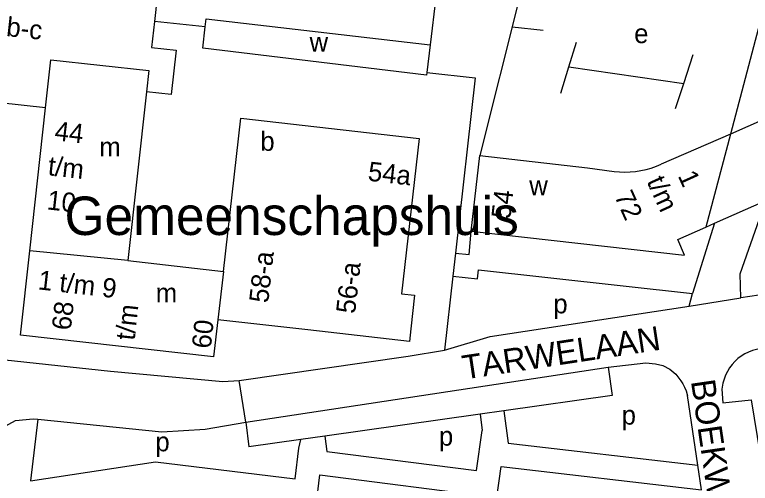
# Model space of a CAD drawing. Extents: x 161936 to 163647, y 386450 to 388633.
# Drawn here: x 162379.9 to 162533, y 387515.7 to 387613.3 of the extents above; entities that cross this region are included whole.
import ezdxf

# ---------------------------------------------------------------- set-up
doc = ezdxf.new("R2010")
doc.units = 0
for name, color, linetype in [('BLT_Basislijn', 7, 'Continuous'), ('BLT_Bebouwing', 7, 'Continuous'), ('BLT_Bebouwing_beschrifting', 7, 'Continuous'), ('BLT_Centroide', 7, 'Continuous'), ('BLT_Huisnummer_reeks', 7, 'Continuous'), ('BLT_Onderdoorgang_en_onderverdeling', 7, 'Continuous'), ('BLT_Onderverdeling_panden', 7, 'Continuous'), ('BLT_Straatnaam', 7, 'Continuous'), ('BLT_Vlakafsluiter', 7, 'Continuous')]:
    doc.layers.add(name, color=color, linetype=linetype)

msp = doc.modelspace()

# ---------------------------------------------------------------- linework, layer by layer
at = {"layer": 'BLT_Basislijn'}
for p, q in [((162468.14, 387621.4), (162466.42, 387606.97)), ((162485.73, 387619.74), (162476.71, 387583.92)), ((162536.08, 387615.52), (162528.92, 387588.41)), ((162419.59, 387610.73), (162408.99, 387611.82)), ((162489.95, 387609.95), (162483.5, 387610.68)), ((162495.3, 387602.42), (162496.9, 387607.57)), ((162519.19, 387598.96), (162521.14, 387604.98)), ((162493.59, 387596.91), (162495.3, 387602.42)), ((162495.3, 387602.42), (162519.19, 387598.96)), ((162517.5, 387593.75), (162519.19, 387598.96)), ((162525.58, 387569.83), (162521.02, 387555.2)), ((162589.75, 387563.33), (162531.07, 387554.28)), ((162471.15, 387558.82), (162476.28, 387558.27)), ((162520.33, 387552.58), (162521.02, 387555.2)), ((162520.33, 387552.58), (162531.07, 387554.28)), ((162478.9, 387546.27), (162520.33, 387552.58)), ((162461.82, 387542.19), (162469.41, 387543.41)), ((162428.06, 387528.41), (162503.48, 387539.9)), ((162520.51, 387530.22), (162519.95, 387533.99)), ((162481.74, 387530.77), (162482.64, 387524.07)), ((162384.71, 387529.03), (162383.23, 387516.23)), ((162476.79, 387530.07), (162477.24, 387526.7)), ((162522.11, 387519.43), (162520.51, 387530.22)), ((162428.06, 387528.41), (162428.65, 387523.26)), ((162444.46, 387525.49), (162444.89, 387522.28)), ((162482.64, 387524.07), (162522.11, 387519.43)), ((162522.87, 387514.31), (162522.11, 387519.43))]:
    msp.add_line(p, q, dxfattribs=at)
for points in [[(162465.74, 387601.24), (162475.8, 387600.1), (162471.69, 387563.62)], [(162531.07, 387554.28), (162530.95, 387559.32), (162534.98, 387570.76)], [(162471.69, 387563.62), (162474.51, 387563.31), (162474.91, 387568.22)], [(162471.69, 387563.62), (162471.15, 387558.82)], [(162476.28, 387558.27), (162476.48, 387560.14), (162521.02, 387555.2)], [(162471.15, 387558.82), (162469.41, 387543.41)], [(162296, 387550.24), (162399.89, 387539.03), (162423.22, 387536.85), (162426.68, 387537.12)], [(162469.41, 387543.41), (162478.9, 387546.27)], [(162536.91, 387543.84), (162536.04, 387543.83), (162535.17, 387543.74), (162534.32, 387543.58), (162533.49, 387543.34), (162532.68, 387543.02), (162531.9, 387542.63), (162531.16, 387542.17), (162530.47, 387541.64), (162529.83, 387541.05), (162529.25, 387540.41), (162528.73, 387539.71), (162528.27, 387538.97), (162527.88, 387538.19), (162527.57, 387537.38), (162527.33, 387536.55), (162527.18, 387535.69), (162527.13, 387535.27)], [(162426.68, 387537.12), (162461.82, 387542.19)], [(162503.48, 387539.9), (162504.32, 387533.96), (162481.74, 387530.77)], [(162503.48, 387539.9), (162511.27, 387540.76), (162513.29, 387540.55), (162514.83, 387540.2), (162516.26, 387539.46), (162517.52, 387538.39), (162518.55, 387537.03), (162518.99, 387536.38), (162519.37, 387535.68), (162519.67, 387534.95), (162519.9, 387534.2), (162519.95, 387533.99)], [(162527.13, 387535.27), (162527.33, 387532.42), (162533.24, 387533.03), (162539.56, 387494.49), (162533.85, 387493.27), (162533.85, 387492.66)], [(162481.74, 387530.77), (162476.79, 387530.07)], [(162373.99, 387508.61), (162375.7, 387523.78), (162377.33, 387527.26), (162380.06, 387528.76), (162383.74, 387529.11), (162384.71, 387529.03)], [(162384.71, 387529.03), (162410.55, 387526.4), (162419.57, 387526.94), (162428.06, 387528.41)], [(162476.79, 387530.07), (162444.46, 387525.49)], [(162444.89, 387522.28), (162476.02, 387518.32), (162477.24, 387526.7)], [(162439.51, 387524.79), (162428.65, 387523.26)], [(162438.32, 387516.61), (162439.09, 387523.02), (162439.51, 387524.79)], [(162444.46, 387525.49), (162439.51, 387524.79)], [(162383.23, 387516.23), (162409.21, 387520.18), (162438.32, 387516.61)], [(162442.69, 387511.03), (162443.45, 387517.42), (162480.25, 387512.74), (162481.2, 387519.2), (162522.87, 387514.31)]]:
    msp.add_lwpolyline(points, dxfattribs=at)
at = {"layer": 'BLT_Bebouwing'}
for p, q in [((162466.42, 387606.97), (162465.74, 387601.24)), ((162407.37, 387597.19), (162403.49, 387562.1)), ((162383.09, 387564.11), (162386.35, 387593.85)), ((162536.17, 387591.57), (162528.92, 387588.41)), ((162528.92, 387588.41), (162514.52, 387582.13)), ((162474.91, 387568.22), (162476.71, 387583.92)), ((162476.71, 387583.92), (162499.13, 387581.4)), ((162499.13, 387581.4), (162504.68, 387580.64)), ((162525.58, 387569.83), (162536.17, 387574.5)), ((162517.96, 387566.47), (162523.76, 387569.03)), ((162523.76, 387569.03), (162525.58, 387569.83)), ((162474.91, 387568.22), (162519.34, 387563.18)), ((162519.34, 387563.18), (162517.96, 387566.47)), ((162381.16, 387546.55), (162383.09, 387564.11))]:
    msp.add_line(p, q, dxfattribs=at)
for points in [[(162385.34, 387629.29), (162410.61, 387626.48), (162408.99, 387611.82)], [(162386.35, 387593.85), (162362.83, 387596.44), (162364.53, 387611.92)], [(162408.99, 387611.82), (162408.39, 387606.43), (162413.5, 387605.87), (162412.48, 387596.62), (162407.37, 387597.19)], [(162419.59, 387610.73), (162419.78, 387612.42), (162466.42, 387606.97)], [(162465.74, 387601.24), (162465.67, 387600.71), (162419.1, 387606.29), (162419.59, 387610.73)], [(162423.38, 387559.76), (162426.97, 387591.7), (162464.13, 387587.52), (162460.46, 387555.14)], [(162504.68, 387580.64), (162505.79, 387580.54), (162506.91, 387580.51), (162508.03, 387580.54), (162509.15, 387580.64), (162510.26, 387580.81), (162511.36, 387581.04), (162512.44, 387581.34), (162513.5, 387581.71), (162514.52, 387582.13)], [(162403.49, 387562.1), (162423.38, 387559.76)], [(162460.46, 387555.14), (162463.16, 387554.84), (162462.37, 387547.82)], [(162422.18, 387549.71), (162421.33, 387542.05), (162381.16, 387546.55)], [(162440.93, 387547.61), (162422.18, 387549.71)], [(162462.08, 387545.24), (162440.93, 387547.61)], [(162462.37, 387547.82), (162462.08, 387545.24)]]:
    msp.add_lwpolyline(points, dxfattribs=at)
at = {"layer": 'BLT_Onderdoorgang_en_onderverdeling'}
msp.add_line((162528.92, 387588.41), (162523.76, 387569.03), dxfattribs=at)
at = {"layer": 'BLT_Onderverdeling_panden'}
for p, q in [((162403.49, 387562.1), (162383.09, 387564.11)), ((162423.38, 387559.76), (162422.18, 387549.71))]:
    msp.add_line(p, q, dxfattribs=at)
msp.add_lwpolyline([(162386.35, 387593.85), (162387.45, 387603.87), (162407.86, 387601.63), (162407.37, 387597.19)], dxfattribs=at)
at = {"layer": 'BLT_Vlakafsluiter'}
msp.add_line((162428.06, 387528.41), (162426.68, 387537.12), dxfattribs=at)

# ---------------------------------------------------------------- texts
at = {"layer": 'BLT_Bebouwing_beschrifting'}
msp.add_text('Gemeenschapshuis', height=8, dxfattribs=at).set_placement((162390.3, 387567.39))
at = {"layer": 'BLT_Centroide'}
for s, p in [('e', (162508.87, 387607.35)), ('w', (162441.3, 387605.58)), ('b', (162431.06, 387584.92)), ('m', (162397.54, 387583.74)), ('w', (162487.03, 387575.68)), ('m', (162409.28, 387553.34)), ('p', (162492.05, 387551.07)), ('p', (162506.27, 387527.9)), ('p', (162468.23, 387523.52)), ('p', (162409.21, 387522.34))]:
    msp.add_text(s, height=4, dxfattribs=at).set_placement(p)
at = {"layer": 'BLT_Huisnummer_reeks'}
for s, rotation, p in [('46-a-b-c', 353.698, (162365.63, 387610.22)), ('44', 353.5974, (162388.1, 387587.13)), ('t/m', 353.5325, (162386.71, 387579.87)), ('54a', 353.5974, (162453.31, 387578.72)), ('t/m', 294.3347, (162511.42, 387578.59)), ('1', 294.3347, (162517.9, 387579.74)), ('10', 353.5976, (162386.52, 387572.74)), ('54', 83.602, (162483.09, 387570.63)), ('72', 294.3347, (162504.67, 387575.53)), ('58-a', 83.5967, (162432.68, 387553.12)), ('56-a', 83.602, (162450.77, 387550.88)), ('1 t/m 9', 353.4798, (162384.65, 387556.09)), ('68', 83.4815, (162391.58, 387547.42)), ('t/m ', 83.7795, (162404.87, 387545.34)), ('60', 83.7795, (162420.73, 387543.61))]:
    msp.add_text(s, height=4, rotation=rotation, dxfattribs=at).set_placement(p)
at = {"layer": 'BLT_Straatnaam'}
for s, rotation, p in [('TARWELAAN', 8.6191, (162473.48, 387537.29)), ('BOEKWEITSTRAAT', 278.2054, (162520.68, 387536.97))]:
    msp.add_text(s, height=5, rotation=rotation, dxfattribs=at).set_placement(p)

doc.saveas('drawing.dxf')
